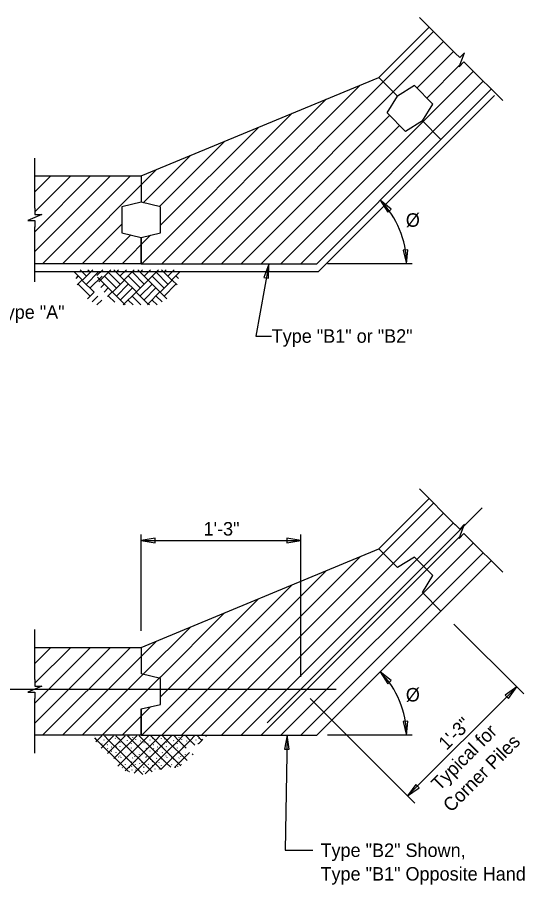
# Model space of a CAD drawing. Extents: x 0.4 to 30.4, y 0.1 to 19.4.
# Drawn here: x 10.94 to 16.63, y 0.42 to 10.14 of the extents above; entities that cross this region are included whole.
import ezdxf

# ---------------------------------------------------------------- set-up
doc = ezdxf.new("R2010")
doc.units = 0
for name, color, linetype in [('Dimension', 7, 'Continuous'), ('Miscellaneous', 7, 'Continuous'), ('SheetPileConc', 7, 'Continuous'), ('TextStructures', 7, 'Continuous')]:
    doc.layers.add(name, color=color, linetype=linetype)

msp = doc.modelspace()

# ---------------------------------------------------------------- linework, layer by layer
at = {"layer": 'Dimension'}
for p, q in [((15.4473, 10.1428), (15.8492, 9.7409)), ((15.9982, 9.5919), (16.3805, 9.2096)), ((14.3167, 7.295), (16.2894, 9.2679)), ((11.1364, 8.0057), (11.1364, 8.5658)), ((11.1364, 7.1795), (11.1364, 7.7951)), ((11.1364, 7.295), (14.3167, 7.295)), ((15.3652, 7.3812), (14.416, 7.3812)), ((15.4473, 4.8586), (15.8492, 4.4567)), ((12.3278, 3.2671), (12.3278, 4.3456)), ((12.3278, 4.2799), (14.1178, 4.2799)), ((14.1178, 2.7541), (14.1178, 4.3456)), ((15.9982, 4.3077), (16.3805, 3.9254)), ((15.8338, 3.3439), (16.6166, 2.5612)), ((11.1364, 2.7215), (11.1364, 3.2816)), ((15.315, 1.4172), (16.5378, 2.64)), ((11.1364, 1.8953), (11.1364, 2.5109)), ((14.2235, 2.5087), (15.3938, 1.3384)), ((15.3652, 2.097), (14.416, 2.097))]:
    msp.add_line(p, q, dxfattribs=at)
for points in [[(15.998, 9.5921), (15.9467, 9.6434), (15.8919, 9.5886), (15.9229, 9.6672), (15.9538, 9.7459), (15.899, 9.6911), (15.8478, 9.7423)], [(11.1364, 8.0055), (11.1364, 7.933), (11.2139, 7.933), (11.1364, 7.8993), (11.0589, 7.8655), (11.1364, 7.8655), (11.1364, 7.793)], [(13.7593, 7.3769), (13.6131, 6.5692), (13.7903, 6.5692)], [(15.998, 4.3079), (15.9467, 4.3592), (15.8919, 4.3044), (15.9229, 4.383), (15.9538, 4.4617), (15.899, 4.4069), (15.8478, 4.4581)], [(11.1364, 2.7213), (11.1364, 2.6488), (11.2139, 2.6488), (11.1364, 2.615), (11.0589, 2.5813), (11.1364, 2.5813), (11.1364, 2.5088)], [(13.9657, 2.097), (13.9426, 0.8111), (14.2532, 0.8111)]]:
    msp.add_lwpolyline(points, dxfattribs=at)
for points in [[(15.0078, 8.0922), (15.0925, 7.9584), (15.1318, 7.9937)], [(15.3028, 7.3805), (15.3176, 7.5382), (15.2648, 7.5342)], [(13.7593, 7.3769), (13.7027, 7.2289), (13.7546, 7.2186)], [(12.3278, 4.2798), (12.484, 4.2534), (12.484, 4.3063)], [(14.1178, 4.2798), (13.9616, 4.3063), (13.9616, 4.2534)], [(15.0078, 2.808), (15.0925, 2.6741), (15.1318, 2.7095)], [(16.5378, 2.64), (16.4086, 2.5483), (16.446, 2.5108)], [(15.3028, 2.0962), (15.3176, 2.254), (15.2648, 2.25)], [(13.9657, 2.097), (13.9356, 1.9415), (13.9885, 1.9403)], [(15.315, 1.4172), (15.4442, 1.509), (15.4067, 1.5464)]]:
    msp.add_lwpolyline(points, close=True, dxfattribs=at)
for centre in [(14.2966, 7.3812), (14.2966, 2.097)]:
    msp.add_arc(centre, 1.0053, 0, 45.00083, dxfattribs=at)
at = {"layer": 'Miscellaneous'}
for p, q in [((13.004, 7.3812), (15.6065, 9.9836)), ((13.2268, 7.3812), (15.7178, 9.8723)), ((15.4182, 9.35), (15.8292, 9.7609)), ((13.8949, 7.3812), (16.0519, 9.5382)), ((15.5296, 9.2386), (15.9007, 9.6097)), ((12.7813, 7.3812), (14.7824, 9.3823)), ((14.1177, 7.3812), (16.1633, 9.4268)), ((12.5586, 7.3812), (14.4022, 9.2248)), ((12.3358, 7.3812), (14.0219, 9.0673)), ((13.4495, 7.3812), (15.112, 9.0437)), ((12.5444, 7.8125), (13.6417, 8.9098)), ((13.6723, 7.3812), (15.2233, 8.9324)), ((12.5313, 8.0222), (13.2615, 8.7524)), ((12.3512, 8.0648), (12.8813, 8.5949)), ((11.1364, 7.7409), (11.7611, 8.3657)), ((11.1364, 7.5182), (11.9838, 8.3657)), ((11.1364, 8.1864), (11.3156, 8.3657)), ((11.1364, 7.9637), (11.5383, 8.3657)), ((11.2222, 7.3812), (12.2065, 8.3657)), ((11.4449, 7.3812), (12.501, 8.4374)), ((11.6676, 7.3812), (12.1113, 7.8249)), ((11.8904, 7.3812), (12.2128, 7.7037)), ((12.1131, 7.3812), (12.4333, 7.7016)), ((11.5768, 7.2907), (11.6664, 7.2011)), ((11.6426, 7.3132), (11.7105, 7.2453)), ((11.7841, 7.3132), (11.6692, 7.1983)), ((11.7311, 7.3132), (11.7548, 7.2895)), ((11.8324, 7.2482), (11.8974, 7.3132)), ((11.9859, 7.3132), (11.8519, 7.1792)), ((12.0204, 7.3132), (12.1353, 7.1983)), ((12.0733, 7.3132), (12.0497, 7.2895)), ((12.1619, 7.3132), (12.0939, 7.2453)), ((12.2501, 7.3132), (12.138, 7.2011)), ((12.5211, 7.3132), (12.2735, 7.0657)), ((12.2904, 7.3132), (12.5379, 7.0658)), ((12.3174, 7.2863), (12.3442, 7.3132)), ((12.3615, 7.2422), (12.4325, 7.3132)), ((12.5555, 7.3132), (12.6704, 7.1983)), ((12.6085, 7.3132), (12.5848, 7.2895)), ((12.697, 7.3132), (12.629, 7.2453)), ((12.7627, 7.2907), (12.6732, 7.2011)), ((11.6193, 7.2426), (11.5939, 7.2172)), ((11.6636, 7.1983), (11.61, 7.1447)), ((11.7989, 7.063), (11.6664, 7.1955)), ((11.8456, 7.2861), (11.7135, 7.1541)), ((11.8897, 7.242), (11.7576, 7.1099)), ((11.8372, 7.2313), (12.0027, 7.0658)), ((11.9148, 7.242), (12.0468, 7.1099)), ((11.9589, 7.2861), (12.091, 7.1541)), ((12.0055, 7.063), (12.138, 7.1955)), ((12.1408, 7.1983), (12.2735, 7.0657)), ((12.1851, 7.2426), (12.3178, 7.1099)), ((12.2292, 7.2867), (12.3619, 7.1541)), ((12.4499, 7.242), (12.582, 7.1099)), ((12.494, 7.2861), (12.6261, 7.1541)), ((12.5406, 7.063), (12.6732, 7.1955)), ((12.676, 7.1983), (12.7296, 7.1447)), ((12.7202, 7.2426), (12.7456, 7.2172)), ((11.7547, 7.0187), (11.6222, 7.1512)), ((11.9143, 7.1542), (11.8755, 7.1153)), ((11.9586, 7.1099), (11.9136, 7.0649)), ((12.0498, 7.0187), (12.1823, 7.1512)), ((12.0939, 6.9746), (12.2264, 7.1071)), ((12.4494, 7.1542), (12.3172, 7.0219)), ((12.4937, 7.1099), (12.3615, 6.9776)), ((12.5849, 7.0187), (12.7174, 7.1512)), ((11.7989, 7.063), (11.7255, 6.9896)), ((11.8428, 7.0192), (11.7775, 6.9538)), ((12.0027, 7.0658), (11.9517, 7.0147)), ((11.9617, 7.0192), (12.0308, 6.95)), ((12.0055, 7.063), (12.1473, 6.9213)), ((12.2707, 7.0629), (12.1273, 6.9195)), ((12.2264, 7.0186), (12.3256, 6.9195)), ((12.2707, 7.0629), (12.4028, 6.9307)), ((12.5379, 7.0658), (12.4056, 6.9335)), ((12.4968, 7.0192), (12.5621, 6.9538)), ((12.5406, 7.063), (12.614, 6.9896)), ((11.8869, 6.975), (11.8313, 6.9195)), ((12.1823, 6.9745), (12.2373, 6.9195)), ((12.3971, 6.9195), (12.4056, 6.928)), ((12.4084, 6.9307), (12.4197, 6.9195)), ((12.4527, 6.975), (12.5082, 6.9195)), ((13.004, 2.097), (15.6065, 4.6994)), ((13.2268, 2.097), (15.7178, 4.5881)), ((16.1502, 4.6468), (13.7399, 2.2366)), ((15.4182, 4.0658), (15.8292, 4.4767)), ((15.5296, 3.9544), (15.9007, 4.3255)), ((13.4495, 2.097), (15.5347, 4.1822)), ((13.8949, 2.097), (16.0519, 4.254)), ((12.7813, 2.097), (14.7824, 4.0981)), ((14.1177, 2.097), (16.1633, 4.1426)), ((12.5586, 2.097), (14.4022, 3.9406)), ((13.6723, 2.097), (15.5296, 3.9544)), ((12.3358, 2.097), (14.0219, 3.7831)), ((12.5444, 2.5283), (13.6417, 3.6256)), ((12.5313, 2.738), (13.2615, 3.4682)), ((12.3512, 2.7806), (12.8813, 3.3107)), ((11.4449, 2.097), (12.501, 3.1532)), ((11.1364, 2.4567), (11.7611, 3.0814)), ((11.1364, 2.234), (11.9838, 3.0814)), ((11.1364, 2.9022), (11.3156, 3.0814)), ((11.1364, 2.6795), (11.5383, 3.0814)), ((11.2222, 2.097), (12.2065, 3.0814)), ((11.6676, 2.097), (12.3512, 2.7806)), ((11.8904, 2.097), (12.5444, 2.7511)), ((10.7426, 2.6144), (11.1364, 2.6144)), ((11.1364, 2.6144), (14.5141, 2.6144)), ((12.1131, 2.097), (12.4333, 2.4173)), ((11.805, 2.0789), (11.8055, 2.0814)), ((11.8356, 2.0407), (11.8072, 2.0691)), ((11.8356, 2.0407), (11.8858, 2.091)), ((11.8769, 2.0709), (11.8754, 2.0717)), ((11.9115, 2.0438), (11.9085, 2.0424)), ((11.9658, 2.0407), (11.9155, 2.0911)), ((11.943, 2.0626), (11.9423, 2.0641)), ((11.9658, 2.0407), (12.0164, 2.0914)), ((11.9799, 2.0461), (11.9806, 2.0491)), ((12.0373, 2.0621), (12.0381, 2.0651)), ((12.0957, 2.041), (12.0452, 2.0915)), ((12.0735, 2.0543), (12.0742, 2.0574)), ((12.096, 2.0407), (12.1471, 2.0918)), ((12.2262, 2.0407), (12.175, 2.0919)), ((12.1945, 2.0867), (12.19, 2.0859)), ((12.2262, 2.0407), (12.2777, 2.0923)), ((12.2359, 2.0739), (12.2351, 2.0754)), ((12.2667, 2.0506), (12.2674, 2.0536)), ((12.3564, 2.0407), (12.3048, 2.0924)), ((12.3216, 2.0777), (12.3224, 2.0814)), ((12.3564, 2.0407), (12.4084, 2.0927)), ((12.3938, 2.0709), (12.3923, 2.0717)), ((12.4284, 2.0438), (12.4254, 2.0424)), ((12.4866, 2.0407), (12.4345, 2.0928)), ((12.4599, 2.0626), (12.4592, 2.0641)), ((12.4866, 2.0407), (12.539, 2.0932)), ((12.4968, 2.0461), (12.4975, 2.0491)), ((12.5542, 2.0621), (12.555, 2.0651)), ((12.6166, 2.041), (12.5643, 2.0933)), ((12.5904, 2.0543), (12.5911, 2.0574)), ((12.6168, 2.0407), (12.6697, 2.0936)), ((12.747, 2.0407), (12.6941, 2.0937)), ((12.7114, 2.0867), (12.7069, 2.0859)), ((12.747, 2.0407), (12.8003, 2.0941)), ((12.7527, 2.0739), (12.752, 2.0754)), ((12.7836, 2.0506), (12.7843, 2.0536)), ((12.8772, 2.0407), (12.8239, 2.0941)), ((12.8385, 2.0777), (12.8393, 2.0814)), ((12.8772, 2.0407), (12.931, 2.0945)), ((12.9107, 2.0709), (12.9092, 2.0717)), ((12.9453, 2.0438), (12.9423, 2.0424)), ((13.0074, 2.0407), (12.9536, 2.0946)), ((12.9768, 2.0626), (12.9761, 2.0641)), ((13.0074, 2.0407), (13.0189, 2.0522)), ((13.0137, 2.0461), (13.0144, 2.0491)), ((13.0512, 2.0845), (13.0616, 2.0949)), ((11.8179, 2.0231), (11.8356, 2.0407)), ((12.096, 1.7803), (11.8356, 2.0407)), ((11.8423, 2.0152), (11.843, 2.0183)), ((11.8785, 1.9534), (11.9658, 2.0407)), ((11.8897, 1.998), (11.8859, 1.9973)), ((11.9318, 1.9995), (11.9303, 2.0017)), ((11.9499, 1.8947), (12.096, 2.0407)), ((11.9505, 1.9927), (11.9521, 1.9957)), ((11.9505, 1.9453), (11.9521, 1.9484)), ((12.096, 1.9105), (11.9658, 2.0407)), ((11.994, 1.9634), (11.9902, 1.9626)), ((12.0532, 1.9634), (12.0494, 1.9626)), ((12.0666, 2.0017), (12.0674, 2.0047)), ((12.0923, 2.0168), (12.093, 2.0198)), ((12.0923, 1.9686), (12.093, 1.9717)), ((12.4504, 1.6863), (12.096, 2.0407)), ((12.096, 1.7803), (12.3564, 2.0407)), ((12.096, 1.9105), (12.2262, 2.0407)), ((12.1467, 1.7008), (12.4866, 2.0407)), ((12.1742, 2.0355), (12.1757, 2.0386)), ((12.1742, 1.9882), (12.1757, 1.9912)), ((12.1795, 1.9611), (12.1765, 1.9604)), ((12.2186, 2.0017), (12.2186, 2.0047)), ((12.2186, 1.9543), (12.2186, 1.9573)), ((12.5531, 1.7138), (12.2262, 2.0407)), ((12.2359, 2.0265), (12.2351, 2.028)), ((12.2502, 1.6741), (12.6168, 2.0407)), ((12.2772, 1.9596), (12.2735, 1.9588)), ((12.3216, 2.0303), (12.3224, 2.034)), ((12.6168, 1.7803), (12.3564, 2.0407)), ((12.3592, 2.0152), (12.3599, 2.0183)), ((12.3855, 1.9499), (12.387, 1.9528)), ((12.387, 1.9484), (12.3877, 1.9514)), ((12.4066, 1.998), (12.4028, 1.9973)), ((12.4487, 1.9995), (12.4472, 2.0017)), ((12.4674, 1.9927), (12.469, 1.9957)), ((12.4674, 1.9453), (12.469, 1.9484)), ((12.6168, 1.9105), (12.4866, 2.0407)), ((12.5109, 1.9634), (12.5071, 1.9626)), ((12.5701, 1.9634), (12.5663, 1.9626)), ((12.5835, 2.0017), (12.5843, 2.0047)), ((12.6092, 2.0168), (12.6099, 2.0198)), ((12.6092, 1.9686), (12.6099, 1.9717)), ((12.8415, 1.816), (12.6168, 2.0407)), ((12.6168, 1.7803), (12.8772, 2.0407)), ((12.6168, 1.9105), (12.747, 2.0407)), ((12.6911, 2.0355), (12.6926, 2.0386)), ((12.6911, 1.9882), (12.6926, 1.9912)), ((12.6964, 1.9611), (12.6934, 1.9604)), ((12.7355, 2.0017), (12.7355, 2.0047)), ((12.7355, 1.9543), (12.7355, 1.9573)), ((12.8333, 1.9544), (12.747, 2.0407)), ((12.7527, 2.0265), (12.752, 2.028)), ((12.7941, 1.9596), (12.7904, 1.9588)), ((12.8385, 2.0303), (12.8393, 2.034)), ((12.8761, 2.0152), (12.8768, 2.0183)), ((12.9297, 1.9883), (12.8772, 2.0407)), ((12.9234, 1.998), (12.9197, 1.9973)), ((12.9648, 2.0006), (12.9641, 2.0017)), ((12.9687, 2.002), (13.0074, 2.0407)), ((13.0118, 2.0363), (13.0074, 2.0407)), ((11.994, 1.916), (11.9902, 1.9152)), ((12.0213, 1.8359), (12.096, 1.9105)), ((12.0475, 1.9002), (12.0483, 1.9032)), ((12.0652, 1.8739), (12.0614, 1.8732)), ((12.072, 1.8513), (12.0715, 1.8522)), ((12.0907, 1.8648), (12.0915, 1.8679)), ((12.3478, 1.6587), (12.096, 1.9105)), ((12.1021, 1.843), (12.1036, 1.8468)), ((12.1178, 1.931), (12.1133, 1.931)), ((12.1351, 1.8717), (12.1359, 1.8746)), ((12.1517, 1.9017), (12.1502, 1.9025)), ((12.2268, 1.9032), (12.2276, 1.9062)), ((12.2562, 1.9077), (12.2554, 1.9092)), ((12.2562, 1.8604), (12.2554, 1.8619)), ((12.3088, 1.9032), (12.3096, 1.9062)), ((12.3088, 1.8792), (12.3096, 1.8821)), ((12.3366, 1.9318), (12.3389, 1.9348)), ((12.3366, 1.8844), (12.3389, 1.8874)), ((12.3714, 1.6651), (12.6168, 1.9105)), ((12.3833, 1.8453), (12.3847, 1.8484)), ((12.387, 1.8611), (12.3877, 1.8641)), ((12.4156, 1.8551), (12.4171, 1.8588)), ((12.4284, 1.9198), (12.4269, 1.9221)), ((12.4667, 1.8874), (12.466, 1.8889)), ((12.4698, 1.8897), (12.4667, 1.8897)), ((12.5109, 1.916), (12.5071, 1.9152)), ((12.5644, 1.9002), (12.5652, 1.9032)), ((12.5821, 1.8739), (12.5783, 1.8732)), ((12.5889, 1.8513), (12.5884, 1.8522)), ((12.6076, 1.8648), (12.6084, 1.8679)), ((12.7737, 1.7536), (12.6168, 1.9105)), ((12.619, 1.843), (12.6205, 1.8468)), ((12.6347, 1.931), (12.6302, 1.931)), ((12.652, 1.8717), (12.6527, 1.8746)), ((12.6686, 1.9017), (12.6671, 1.9025)), ((12.7016, 1.7349), (12.8705, 1.9038)), ((12.7437, 1.9032), (12.7445, 1.9062)), ((12.7731, 1.9077), (12.7723, 1.9092)), ((12.7731, 1.8604), (12.7723, 1.8619)), ((12.8257, 1.9032), (12.8264, 1.9062)), ((12.8257, 1.8792), (12.8264, 1.8821)), ((12.8535, 1.8844), (12.8558, 1.8874)), ((12.9093, 1.8785), (12.9009, 1.8868)), ((12.046, 1.8273), (12.0467, 1.8303)), ((12.0668, 1.7511), (12.096, 1.7803)), ((12.072, 1.804), (12.0712, 1.8055)), ((12.1855, 1.6908), (12.096, 1.7803)), ((12.152, 1.7675), (12.1528, 1.7704)), ((12.1525, 1.8401), (12.154, 1.843)), ((12.1765, 1.8273), (12.1728, 1.8265)), ((12.2224, 1.7957), (12.2201, 1.798)), ((12.2224, 1.7484), (12.2201, 1.7506)), ((12.2359, 1.843), (12.2321, 1.8415)), ((12.2622, 1.8085), (12.263, 1.8115)), ((12.263, 1.7716), (12.2637, 1.7747)), ((12.3118, 1.8288), (12.3134, 1.8325)), ((12.3118, 1.7814), (12.3134, 1.7852)), ((12.3389, 1.7897), (12.3396, 1.7927)), ((12.4111, 1.7723), (12.4073, 1.7716)), ((12.4351, 1.8227), (12.4359, 1.8258)), ((12.4532, 1.801), (12.451, 1.8017)), ((12.4532, 1.7536), (12.451, 1.7544)), ((12.5006, 1.8378), (12.5021, 1.8408)), ((12.5006, 1.7904), (12.5021, 1.7934)), ((12.53, 1.7887), (12.5308, 1.7918)), ((12.5493, 1.7128), (12.6168, 1.7803)), ((12.5539, 1.7605), (12.5546, 1.7635)), ((12.5629, 1.8273), (12.5636, 1.8303)), ((12.5889, 1.804), (12.5881, 1.8055)), ((12.6586, 1.7385), (12.6168, 1.7803)), ((12.6689, 1.7675), (12.6697, 1.7704)), ((12.6693, 1.8401), (12.6708, 1.843)), ((12.6934, 1.8273), (12.6897, 1.8265)), ((12.7393, 1.7957), (12.737, 1.798)), ((12.7393, 1.7484), (12.737, 1.7506)), ((12.7527, 1.843), (12.749, 1.8415)), ((12.7791, 1.8085), (12.7799, 1.8115)), ((12.7799, 1.7716), (12.7806, 1.7747)), ((12.8287, 1.8288), (12.8303, 1.8325)), ((12.1163, 1.7325), (12.117, 1.7356)), ((12.1998, 1.7356), (12.196, 1.7348)), ((12.1998, 1.6882), (12.1974, 1.6877)), ((12.2268, 1.7062), (12.2276, 1.7093)), ((12.2667, 1.7062), (12.2674, 1.7093)), ((12.302, 1.7111), (12.3028, 1.7141)), ((12.3577, 1.7363), (12.3592, 1.7393)), ((12.3577, 1.6889), (12.3592, 1.6919)), ((12.3592, 1.7415), (12.3599, 1.7446)), ((12.4141, 1.704), (12.4111, 1.7032)), ((12.4122, 1.7346), (12.4129, 1.7375)), ((12.4366, 1.7055), (12.4373, 1.7085)), ((12.4855, 1.719), (12.4863, 1.722)), ((12.5317, 1.7169), (12.5332, 1.7199)), ((12.6339, 1.7355), (12.6339, 1.7356)), ((12.7167, 1.7356), (12.7129, 1.7348))]:
    msp.add_line(p, q, dxfattribs=at)
at = {"layer": 'SheetPileConc'}
for p, q in [((14.9926, 9.4694), (15.5566, 10.0335)), ((12.3278, 8.3657), (14.9926, 9.4694)), ((14.9926, 9.4694), (15.2014, 9.2606)), ((15.2014, 9.2606), (14.9926, 9.4694)), ((14.9926, 9.4694), (15.2014, 9.2607)), ((15.3907, 9.3775), (15.2014, 9.2607)), ((15.5967, 9.1716), (15.3907, 9.3775)), ((16.2527, 9.3374), (15.6886, 8.7734)), ((15.0844, 9.0712), (15.2014, 9.2606)), ((15.4798, 8.9822), (15.5967, 9.1716)), ((15.2905, 8.8653), (15.0844, 9.0712)), ((15.4798, 8.9822), (15.2905, 8.8653)), ((15.4798, 8.9822), (15.6886, 8.7734)), ((15.6886, 8.7734), (15.4798, 8.9822)), ((15.6886, 8.7734), (15.4798, 8.9822)), ((14.2965, 7.3812), (15.6886, 8.7734)), ((11.1364, 8.3657), (12.3278, 8.3657)), ((12.3278, 8.3657), (12.3278, 8.0704)), ((12.3278, 8.3657), (12.3278, 8.0703)), ((12.3278, 8.0703), (12.1113, 8.0192)), ((12.5444, 8.0192), (12.3278, 8.0704)), ((12.1113, 8.0192), (12.1113, 7.7278)), ((12.5444, 7.7278), (12.5444, 8.0192)), ((12.1113, 7.7278), (12.3278, 7.6766)), ((12.3278, 7.6766), (12.5444, 7.7278)), ((12.3278, 7.6766), (12.3278, 7.3812)), ((12.3278, 7.3812), (12.3278, 7.6766)), ((12.3278, 7.3812), (11.1364, 7.3812)), ((12.3278, 7.3812), (14.2965, 7.3812)), ((14.9926, 4.1852), (15.5566, 4.7493)), ((12.3278, 3.0814), (14.9926, 4.1852)), ((14.9926, 4.1852), (15.2014, 3.9764)), ((15.2014, 3.9764), (14.9926, 4.1852)), ((14.9926, 4.1852), (15.2014, 3.9764)), ((15.3907, 4.0933), (15.2014, 3.9764)), ((15.5967, 3.8873), (15.3907, 4.0933)), ((16.2527, 4.0532), (15.6886, 3.4892)), ((15.4798, 3.698), (15.5967, 3.8873)), ((15.4798, 3.698), (15.6886, 3.4892)), ((15.6886, 3.4892), (15.4798, 3.698)), ((15.6886, 3.4892), (15.4798, 3.698)), ((14.2965, 2.097), (15.6886, 3.4892)), ((11.1364, 3.0814), (12.3278, 3.0814)), ((12.3278, 3.0814), (12.3278, 2.7861)), ((12.3278, 3.0814), (12.3278, 2.7861)), ((12.5444, 2.7349), (12.3278, 2.7861)), ((12.5444, 2.4436), (12.5444, 2.7349)), ((12.3278, 2.3924), (12.5444, 2.4436)), ((12.3278, 2.3924), (12.3278, 2.097)), ((12.3278, 2.097), (12.3278, 2.3923)), ((12.3278, 2.097), (11.1364, 2.097)), ((12.3278, 2.097), (14.2965, 2.097))]:
    msp.add_line(p, q, dxfattribs=at)

# ---------------------------------------------------------------- texts
at = {"layer": 'Dimension'}
for s, p in [('1\'-3"', (15.7515, 1.922)), ('Typical for', (15.67, 1.4671)), ('Corner Piles', (15.8025, 1.2262))]:
    msp.add_text(s, height=0.1512, rotation=45, dxfattribs=at).set_placement(p)
at = {"layer": 'TextStructures'}
for s, p in [('Ø', (15.2945, 7.7958)), ('Type "A"', (10.6853, 6.7643)), ('Type "B1" or "B2"', (13.7909, 6.496)), ('1\'-3"', (13.0272, 4.3358)), ('Ø', (15.2945, 2.4761)), ('Type "B2" Shown,', (14.3383, 0.7336)), ('Type "B1" Opposite Hand', (14.3383, 0.469))]:
    msp.add_text(s, height=0.1512, dxfattribs=at).set_placement(p)

doc.saveas('drawing.dxf')
